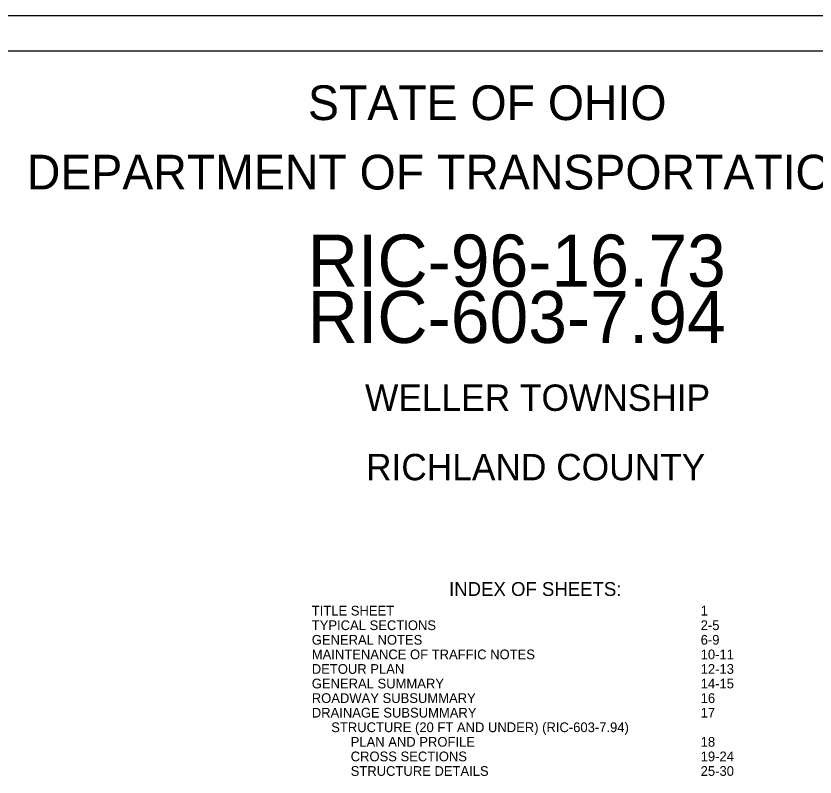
# Model space of a CAD drawing. Extents: x 0 to 70.2, y 0 to 31.4.
# Drawn here: x 9.59 to 21.1, y 11.03 to 22 of the extents above; entities that cross this region are included whole.
import ezdxf

# ---------------------------------------------------------------- set-up
doc = ezdxf.new("R2010")
doc.units = 0
for name, color, linetype in [('SH_Border', 7, 'Continuous'), ('SH_Cut_Line', 7, 'Continuous'), ('SH_Text', 7, 'Continuous')]:
    doc.layers.add(name, color=color, linetype=linetype)

msp = doc.modelspace()

# ---------------------------------------------------------------- linework, layer by layer
at = {"layer": 'SH_Border'}
msp.add_lwpolyline([(1.5, 21.5), (33.5, 21.5), (33.5, 0.5), (1.5, 0.5)], close=True, dxfattribs=at)
at = {"layer": 'SH_Cut_Line'}
msp.add_lwpolyline([(0, 0), (34, 0), (34, 22), (0, 22)], close=True, dxfattribs=at)

# ---------------------------------------------------------------- texts
at = {"layer": 'SH_Text'}
for s, height, p in [('STATE OF OHIO', 0.5, (13.795, 20.5)), ('DEPARTMENT OF TRANSPORTATION', 0.5, (9.747, 19.5)), ('RIC-96-16.73', 0.75, (13.791, 18.1)), ('RIC-603-7.94', 0.75, (13.79, 17.288)), ('WELLER TOWNSHIP', 0.38, (14.617, 16.31)), ('RICHLAND COUNTY', 0.38, (14.631, 15.31)), ('INDEX OF SHEETS:', 0.2, (15.827, 13.643)), ('TITLE SHEET', 0.14, (13.85, 13.361)), ('1', 0.14, (19.45, 13.361)), ('TYPICAL SECTIONS', 0.14, (13.85, 13.151)), ('2-5', 0.14, (19.45, 13.151)), ('GENERAL NOTES', 0.14, (13.85, 12.941)), ('6-9', 0.14, (19.45, 12.941)), ('MAINTENANCE OF TRAFFIC NOTES', 0.14, (13.85, 12.731)), ('10-11', 0.14, (19.45, 12.731)), ('DETOUR PLAN ', 0.14, (13.85, 12.521)), ('12-13', 0.14, (19.45, 12.521)), ('GENERAL SUMMARY', 0.14, (13.85, 12.311)), ('14-15', 0.14, (19.45, 12.311)), ('ROADWAY SUBSUMMARY', 0.14, (13.85, 12.101)), ('16', 0.14, (19.45, 12.101)), ('DRAINAGE SUBSUMMARY', 0.14, (13.85, 11.891)), ('17', 0.14, (19.45, 11.891)), ('STRUCTURE (20 FT AND UNDER) (RIC-603-7.94) ', 0.14, (14.13, 11.681)), ('PLAN AND PROFILE', 0.14, (14.41, 11.471)), ('18', 0.14, (19.45, 11.471)), ('CROSS SECTIONS', 0.14, (14.41, 11.261)), ('19-24', 0.14, (19.45, 11.261)), ('STRUCTURE DETAILS', 0.14, (14.41, 11.051)), ('25-30', 0.14, (19.45, 11.051))]:
    msp.add_text(s, height=height, dxfattribs=at).set_placement(p)

doc.saveas('drawing.dxf')
